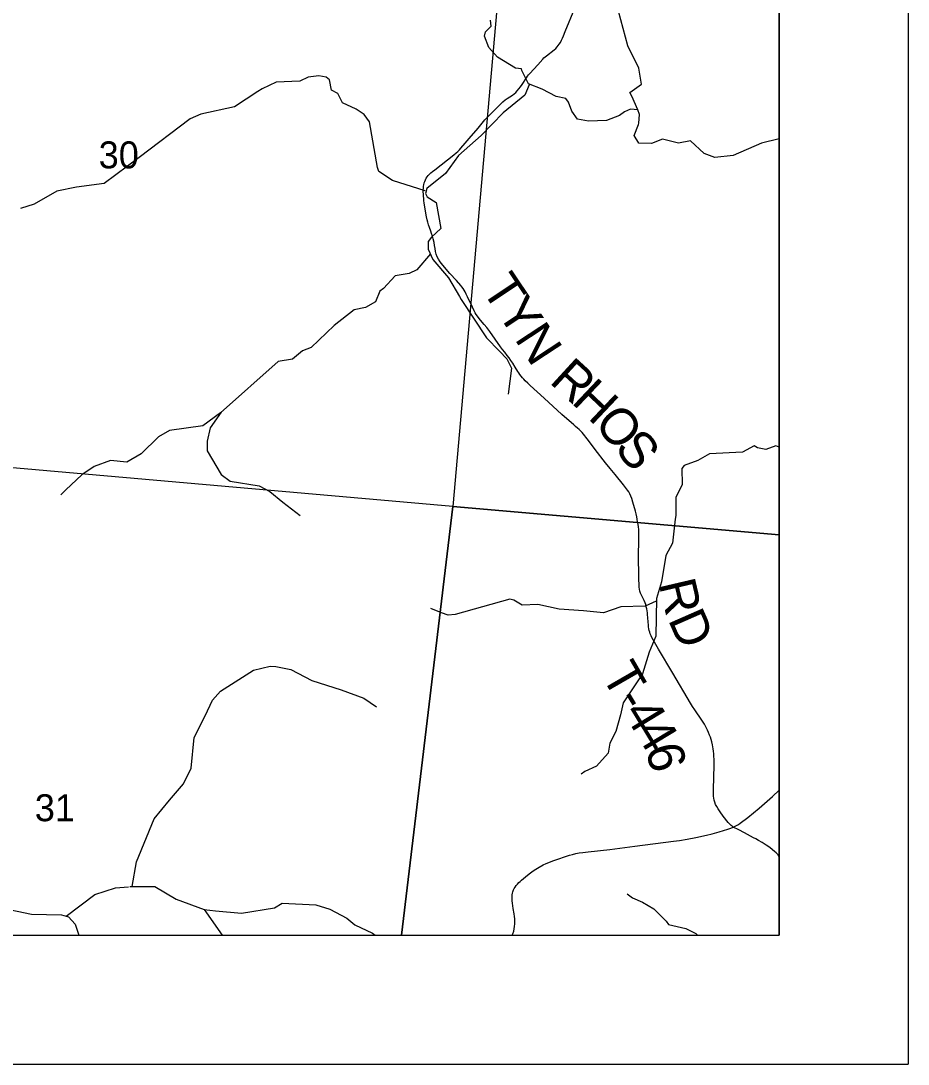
# Model space of a CAD drawing. Extents: x 0 to 42, y 0 to 22.
# Drawn here: x 8.311 to 9, y 14 to 14.81 of the extents above; entities that cross this region are included whole.
import ezdxf

# ---------------------------------------------------------------- set-up
doc = ezdxf.new("R2010")
doc.units = 0
for name, color, linetype in [('GM_X_County_Road', 7, 'Continuous'), ('GM_X_Minor_River', 7, 'Continuous'), ('GM_X_Section', 7, 'Continuous'), ('GM_X_Section_Text', 7, 'Continuous'), ('GM_X_Township_Road', 7, 'Continuous'), ('GM_X_Township_Road_Text', 7, 'Continuous'), ('GM_X_Unincorporated', 7, 'Continuous'), ('SH_Cut_Line', 7, 'Continuous'), ('SH_Data', 7, 'Continuous')]:
    doc.layers.add(name, color=color, linetype=linetype)

msp = doc.modelspace()

# ---------------------------------------------------------------- linework, layer by layer
at = {"layer": 'GM_X_County_Road'}
for points in [[(8.84339, 14.17765), (8.84783, 14.17876), (8.85335, 14.18032), (8.86012, 14.18246), (8.86236, 14.18324), (8.86434, 14.18399), (8.86565, 14.18457), (8.86679, 14.18513), (8.8683, 14.186), (8.86976, 14.18691), (8.87572, 14.19151), (8.8844, 14.19863), (8.89464, 14.20775), (8.9, 14.21265)], [(8.69278, 14.1), (8.6932, 14.10103), (8.69387, 14.10314), (8.69436, 14.105), (8.69464, 14.10693), (8.69478, 14.10893), (8.69478, 14.11093), (8.69471, 14.11272), (8.69457, 14.11465), (8.69431, 14.1167), (8.69351, 14.1207), (8.69312, 14.12288), (8.69286, 14.12485), (8.69272, 14.12665), (8.69262, 14.1283), (8.69258, 14.12984), (8.69272, 14.13149), (8.69297, 14.13272), (8.69325, 14.13384), (8.69374, 14.13514), (8.69427, 14.13623), (8.69497, 14.13735), (8.69581, 14.13851), (8.69672, 14.13967), (8.69781, 14.14086), (8.69883, 14.14181), (8.69988, 14.14271), (8.70455, 14.14653), (8.70701, 14.14843), (8.70911, 14.1499), (8.71115, 14.15134), (8.71353, 14.15278), (8.71689, 14.15457), (8.7191, 14.15566), (8.72107, 14.15653), (8.72293, 14.15727), (8.72509, 14.15809), (8.73708, 14.16205), (8.73953, 14.16276), (8.7421, 14.16337), (8.74468, 14.16389), (8.74753, 14.16432), (8.7496, 14.1646), (8.75181, 14.16484), (8.76845, 14.1666), (8.78795, 14.16911), (8.81792, 14.17292), (8.82255, 14.17358), (8.82859, 14.17461), (8.83533, 14.17593), (8.84339, 14.17765)], [(8.9, 14.16126), (8.89901, 14.16245), (8.89756, 14.16387), (8.89627, 14.16504), (8.89476, 14.16633), (8.89257, 14.16806), (8.88977, 14.17), (8.88663, 14.17206), (8.88394, 14.1736), (8.88179, 14.17474), (8.88003, 14.17563), (8.87302, 14.17947), (8.86864, 14.18181), (8.86434, 14.18399)]]:
    msp.add_lwpolyline(points, dxfattribs=at)
at = {"layer": 'GM_X_Minor_River'}
msp.add_line((8.45369, 14.11999), (8.46759, 14.1), dxfattribs=at)
for points in [[(8.79028, 14.74054), (8.78546, 14.75131), (8.78414, 14.75396), (8.79302, 14.76062), (8.79111, 14.77294), (8.78258, 14.79018), (8.76795, 14.8444)], [(8.9, 14.71819), (8.8861, 14.71467), (8.86415, 14.70514), (8.84995, 14.70359), (8.84162, 14.70662), (8.83101, 14.71648), (8.82173, 14.71475), (8.80942, 14.71796), (8.80091, 14.71453), (8.79106, 14.7147), (8.78727, 14.72078), (8.79067, 14.72914), (8.79105, 14.73028), (8.79161, 14.73693), (8.79028, 14.74054), (8.7846, 14.7411), (8.77987, 14.739), (8.77609, 14.73614), (8.76587, 14.73233), (8.75186, 14.73192), (8.74334, 14.73343), (8.73898, 14.7395), (8.73651, 14.74652), (8.73424, 14.74937), (8.72685, 14.75088), (8.71587, 14.75675), (8.70526, 14.76072), (8.70033, 14.77116), (8.69995, 14.7723), (8.69522, 14.77286), (8.6812, 14.78157), (8.67457, 14.78897), (8.67135, 14.7977), (8.6721, 14.80112), (8.67645, 14.8055), (8.67588, 14.81006)], [(8.62512, 14.67775), (8.59995, 14.68571), (8.58934, 14.69271), (8.58821, 14.69593), (8.58192, 14.73138), (8.57794, 14.73706), (8.57169, 14.74122), (8.5611, 14.74594), (8.5573, 14.75333), (8.55257, 14.75598), (8.55086, 14.76375), (8.5484, 14.76602), (8.54272, 14.76696), (8.5344, 14.76599), (8.52797, 14.76276), (8.50962, 14.76196), (8.49865, 14.75682), (8.49544, 14.75473), (8.47729, 14.74293), (8.451, 14.73719), (8.44287, 14.73357), (8.40318, 14.70372), (8.37596, 14.68337), (8.35458, 14.68048), (8.33945, 14.67742), (8.32187, 14.66733), (8.31109, 14.6639)], [(8.70599, 14.76007), (8.7026, 14.75191), (8.68578, 14.73822), (8.66877, 14.72074), (8.651, 14.70515), (8.64099, 14.6911), (8.62644, 14.6795), (8.6255, 14.67571), (8.62664, 14.67305), (8.63383, 14.66871), (8.63726, 14.64842), (8.63008, 14.64177), (8.62762, 14.63854), (8.62744, 14.63247), (8.63123, 14.62451), (8.64317, 14.61012), (8.65188, 14.59573), (8.65321, 14.59345), (8.67273, 14.56371), (8.68277, 14.5533), (8.68864, 14.54744), (8.69224, 14.54005), (8.68962, 14.51994)], [(8.6292, 14.62876), (8.61875, 14.61633), (8.6127, 14.61367), (8.60192, 14.61175), (8.59285, 14.60187), (8.59002, 14.59997), (8.58662, 14.59162), (8.57887, 14.58724), (8.56998, 14.58551), (8.55448, 14.57334), (8.53672, 14.55605), (8.5301, 14.55357), (8.52235, 14.54711), (8.51119, 14.54519), (8.46644, 14.50544)], [(8.46644, 14.50544), (8.45272, 14.49525), (8.4268, 14.49168), (8.4183, 14.48693), (8.40484, 14.47375), (8.39356, 14.46728), (8.38109, 14.46851), (8.3684, 14.46385), (8.35882, 14.45726), (8.34624, 14.44574), (8.34255, 14.4418)], [(8.46677, 14.50591), (8.45834, 14.49392), (8.45591, 14.48342), (8.45597, 14.47598), (8.46688, 14.45753), (8.47394, 14.45229), (8.49633, 14.44867), (8.50459, 14.4443), (8.51467, 14.436), (8.52805, 14.42575)], [(8.9, 14.47881), (8.89734, 14.47985), (8.88953, 14.47695), (8.88297, 14.47835), (8.8806, 14.47985), (8.87152, 14.47494), (8.84575, 14.47365), (8.83684, 14.46854), (8.82612, 14.4647), (8.82443, 14.46234), (8.82471, 14.44975), (8.81966, 14.43981), (8.81964, 14.42572), (8.81926, 14.42289), (8.81704, 14.40437), (8.812, 14.39462), (8.80871, 14.37428), (8.80459, 14.36142), (8.8043, 14.33211), (8.79908, 14.3197), (8.79394, 14.30291), (8.7789, 14.28051), (8.77673, 14.27114), (8.77319, 14.25824), (8.76858, 14.24922), (8.76709, 14.24132), (8.75822, 14.23126), (8.74919, 14.22711), (8.74638, 14.22502)], [(8.80457, 14.35921), (8.79601, 14.35553), (8.77714, 14.35491), (8.7637, 14.3503), (8.74801, 14.35175), (8.72927, 14.35302), (8.71258, 14.35664), (8.70058, 14.35631), (8.69398, 14.36), (8.69099, 14.36077), (8.64853, 14.349), (8.64297, 14.34842), (8.63796, 14.35029), (8.62964, 14.35371)], [(8.39769, 14.13774), (8.40125, 14.15708), (8.41493, 14.19024), (8.42678, 14.20486), (8.43772, 14.21745), (8.4435, 14.22962), (8.44589, 14.25346), (8.45445, 14.27021), (8.46005, 14.28259), (8.46623, 14.2894), (8.49188, 14.30575), (8.50484, 14.30887), (8.50938, 14.30856), (8.52083, 14.30626), (8.53717, 14.29772), (8.55988, 14.29046), (8.5775, 14.28393), (8.58752, 14.27735)], [(8.12783, 14.14717), (8.13599, 14.15552), (8.1433, 14.15959), (8.1517, 14.15997), (8.17089, 14.14857), (8.20808, 14.13328), (8.22125, 14.12286), (8.23036, 14.11976), (8.24621, 14.11792), (8.27861, 14.12162), (8.29102, 14.1223), (8.31972, 14.11635), (8.3429, 14.11591), (8.34662, 14.11487), (8.3687, 14.13168), (8.38484, 14.13687), (8.39508, 14.13765)], [(8.3961, 14.13773), (8.41534, 14.13784), (8.43199, 14.12814), (8.45369, 14.11999), (8.46256, 14.11901), (8.4826, 14.11726), (8.50838, 14.12142), (8.51431, 14.12482), (8.54029, 14.12362), (8.55109, 14.12022), (8.56431, 14.11323), (8.57061, 14.10804), (8.58443, 14.10158), (8.58638, 14.1)], [(8.78197, 14.13224), (8.786, 14.12914), (8.79378, 14.12575), (8.80271, 14.12046), (8.81221, 14.11101), (8.81411, 14.10836), (8.82739, 14.10516), (8.83517, 14.10139), (8.8366, 14.1)], [(8.34589, 14.11514), (8.34849, 14.1142), (8.35361, 14.10852), (8.35642, 14.1)]]:
    msp.add_lwpolyline(points, dxfattribs=at)
at = {"layer": 'GM_X_Section'}
msp.add_lwpolyline([(8.13021, 14.99178), (8.69178, 14.94189), (8.64678, 14.43282), (8.0839, 14.48217), (8.08411, 14.48421), (8.12984, 14.9874)], close=True, dxfattribs=at)
at = {"layer": 'GM_X_Township_Road'}
msp.add_lwpolyline([(8.05023, 14.1), (8.9, 14.1), (8.9, 16.95771), (8.669, 16.9761), (8.30518, 17.00518), (8.2967, 17.00562), (8.26133, 16.54947), (8.24231, 16.32059), (8.17227, 15.49063), (8.16983, 15.46634), (8.16945, 15.45935), (8.16837, 15.44612), (8.1628, 15.37905), (8.15761, 15.31908), (8.1512, 15.24132), (8.08338, 14.51358), (8.06868, 14.30702)], close=True, dxfattribs=at)
for points in [[(8.62375, 14.67833), (8.62381, 14.67983), (8.62393, 14.68125), (8.62415, 14.68248), (8.62449, 14.68384), (8.62489, 14.68508), (8.62541, 14.68625), (8.62609, 14.68757), (8.62673, 14.68858), (8.62748, 14.68955), (8.62843, 14.69062), (8.62954, 14.69167), (8.63078, 14.69272), (8.63259, 14.6941), (8.64749, 14.70574), (8.64918, 14.70719), (8.65052, 14.70839), (8.65175, 14.70959), (8.65283, 14.71076), (8.65622, 14.71474), (8.65767, 14.71647), (8.65927, 14.71832), (8.66638, 14.72624), (8.67037, 14.73146), (8.67146, 14.73272), (8.67253, 14.73384), (8.6807, 14.74217), (8.68203, 14.74352), (8.68383, 14.74527), (8.6855, 14.74681), (8.68718, 14.74823), (8.68893, 14.74951), (8.69291, 14.7521), (8.69432, 14.7531), (8.69546, 14.75409), (8.69661, 14.75532), (8.69791, 14.75687), (8.69911, 14.75847), (8.7004, 14.76028), (8.70372, 14.76537), (8.70455, 14.76664), (8.70542, 14.76784), (8.70631, 14.76886), (8.71265, 14.77554), (8.7164, 14.77986), (8.71733, 14.78088), (8.71819, 14.78171), (8.71927, 14.78256), (8.72525, 14.7872), (8.72654, 14.78832), (8.72761, 14.78942), (8.72847, 14.79044), (8.72927, 14.79155), (8.73013, 14.79297), (8.73101, 14.79462), (8.73177, 14.79624), (8.73252, 14.79799), (8.73386, 14.80129), (8.74136, 14.8196)], [(8.86434, 14.18399), (8.86338, 14.18465), (8.86255, 14.18532), (8.8615, 14.18634), (8.8604, 14.1876), (8.85652, 14.19237), (8.85416, 14.19569), (8.85257, 14.19806), (8.85143, 14.2), (8.8506, 14.20162), (8.84998, 14.20326), (8.84951, 14.20497), (8.84925, 14.20649), (8.84905, 14.20803), (8.84892, 14.20974), (8.84886, 14.21145), (8.84886, 14.21303), (8.84942, 14.23192), (8.84942, 14.23445), (8.84938, 14.23679), (8.84928, 14.23877), (8.84915, 14.24094), (8.84899, 14.24285), (8.84876, 14.24465), (8.84852, 14.2462), (8.84817, 14.24791), (8.84764, 14.25002), (8.84711, 14.25196), (8.84654, 14.25373), (8.84594, 14.25538), (8.84508, 14.25745), (8.84435, 14.25913), (8.84359, 14.26068), (8.8428, 14.26219), (8.84195, 14.26374), (8.84099, 14.26529), (8.83997, 14.2669), (8.83447, 14.27488), (8.83278, 14.27742), (8.83117, 14.28005), (8.8175, 14.30347), (8.80631, 14.32197), (8.80305, 14.32743), (8.80203, 14.32933), (8.80118, 14.33108), (8.80048, 14.33249), (8.79992, 14.33384), (8.79943, 14.33526), (8.79907, 14.33657), (8.7988, 14.33786), (8.79859, 14.33939), (8.79844, 14.3409), (8.79827, 14.34295), (8.79797, 14.34663), (8.79779, 14.34861), (8.79761, 14.35019), (8.79744, 14.35167), (8.79717, 14.3533), (8.79682, 14.35493), (8.79634, 14.35664), (8.79583, 14.35811), (8.79512, 14.35986), (8.79436, 14.36144), (8.79312, 14.36389), (8.79234, 14.36558), (8.79182, 14.36711), (8.79152, 14.36861), (8.79135, 14.3701), (8.79123, 14.37172), (8.79115, 14.37326), (8.79108, 14.37501), (8.79105, 14.37716), (8.79084, 14.39541), (8.79105, 14.40561), (8.7911, 14.40816), (8.7911, 14.41062), (8.79101, 14.41298), (8.79092, 14.41492), (8.7907, 14.41698), (8.79045, 14.41884), (8.79009, 14.42098), (8.78974, 14.42281), (8.78936, 14.42463), (8.78883, 14.42705), (8.78831, 14.42916), (8.78645, 14.43624), (8.78558, 14.43895), (8.78489, 14.44083), (8.78407, 14.44257), (8.78321, 14.44409), (8.78225, 14.44553), (8.78078, 14.44751), (8.77916, 14.44951), (8.77257, 14.45757), (8.76875, 14.4623), (8.7651, 14.46668), (8.75704, 14.47698), (8.75202, 14.48388), (8.75088, 14.48533), (8.74992, 14.48659), (8.74906, 14.48765), (8.74812, 14.48879), (8.74696, 14.49012), (8.7459, 14.49125), (8.74464, 14.49244), (8.74329, 14.49365), (8.7419, 14.49486), (8.74045, 14.4961), (8.73117, 14.50412), (8.71742, 14.51677), (8.70668, 14.52665), (8.70483, 14.52841), (8.70291, 14.53029), (8.70182, 14.53147), (8.70078, 14.5326), (8.69976, 14.53382), (8.6987, 14.53521), (8.69779, 14.53637), (8.69699, 14.53757), (8.69491, 14.54101), (8.69318, 14.54392), (8.6917, 14.54617), (8.69028, 14.54812), (8.68892, 14.54997), (8.68698, 14.55241), (8.68519, 14.55466), (8.68363, 14.55678), (8.67539, 14.56856), (8.67308, 14.57159), (8.67101, 14.57409), (8.66817, 14.5774), (8.66703, 14.57877), (8.6658, 14.58035), (8.66483, 14.58174), (8.66396, 14.58313), (8.66313, 14.58467), (8.66182, 14.5874), (8.65803, 14.59545), (8.65707, 14.59746), (8.65618, 14.59931), (8.65536, 14.60077), (8.65462, 14.60198), (8.65375, 14.60315), (8.65295, 14.60414), (8.6494, 14.60818), (8.64434, 14.61364), (8.63885, 14.62005), (8.63681, 14.62268), (8.63545, 14.62475), (8.63455, 14.6266), (8.63382, 14.62857), (8.63329, 14.63061), (8.6329, 14.63291), (8.6325, 14.63535), (8.63208, 14.6376), (8.63136, 14.64047), (8.63076, 14.64264), (8.63014, 14.6447), (8.6296, 14.64642), (8.62858, 14.64932), (8.62789, 14.65127), (8.62729, 14.6534), (8.62682, 14.65525), (8.62632, 14.65767), (8.62449, 14.66816), (8.62421, 14.67012), (8.62403, 14.67184), (8.62388, 14.67364), (8.62378, 14.67531), (8.62372, 14.67679), (8.62375, 14.67833)]]:
    msp.add_lwpolyline(points, dxfattribs=at)
at = {"layer": 'GM_X_Unincorporated'}
for points in [[(8.9, 14.41067), (8.9, 14.92449), (8.69178, 14.94189), (8.64678, 14.43282)], [(8.04916, 14.1), (8.60693, 14.1), (8.64678, 14.43282), (8.0839, 14.48217)], [(8.60693, 14.1), (8.9, 14.1), (8.9, 14.41067), (8.64678, 14.43282)]]:
    msp.add_lwpolyline(points, close=True, dxfattribs=at)
at = {"layer": 'SH_Cut_Line'}
msp.add_lwpolyline([(8.24231, 16.32059), (8.17227, 15.49063), (8.16983, 15.46634), (8.16945, 15.45935), (8.16837, 15.44612), (8.1628, 15.37905), (8.15761, 15.31908), (8.1512, 15.24132), (8.08338, 14.51358), (8.06868, 14.30702), (8.05023, 14.1), (8.9, 14.1), (8.9, 20.00639)], dxfattribs=at)
at = {"layer": 'SH_Data'}
for p, q in [((9, 21), (9, 14)), ((8.9, 20.9), (8.9, 14.1)), ((2.1, 14.1), (8.9, 14.1)), ((2, 14), (9, 14))]:
    msp.add_line(p, q, dxfattribs=at)

# ---------------------------------------------------------------- texts
at = {"layer": 'GM_X_Section_Text'}
for s, p in [('30', (8.37182, 14.69518)), ('31', (8.32224, 14.18852))]:
    msp.add_text(s, height=0.020928, rotation=0.00001, dxfattribs=at).set_placement(p)
at = {"layer": 'GM_X_Township_Road_Text'}
for s, rotation, p in [('T', 303.79051, (8.66839, 14.60137)), ('Y', 303.78656, (8.68021, 14.58371)), ('N', 303.2925, (8.69408, 14.56298)), ('R', 317.47769, (8.72083, 14.52923)), ('H', 316.5959, (8.73794, 14.51354)), ('O', 309.61248, (8.75548, 14.49703)), ('S', 308.98669, (8.77137, 14.47783)), ('R', 283.20891, (8.80626, 14.37317)), ('D', 293.71113, (8.81336, 14.34516)), ('T', 299.99392, (8.76147, 14.30187)), ('-', 301.2753, (8.77245, 14.28287)), ('4', 301.30716, (8.77851, 14.27288)), ('4', 301.24356, (8.7876, 14.25794)), ('6', 285.24166, (8.79586, 14.2449))]:
    msp.add_text(s, height=0.02841, rotation=rotation, dxfattribs=at).set_placement(p)

doc.saveas('drawing.dxf')
